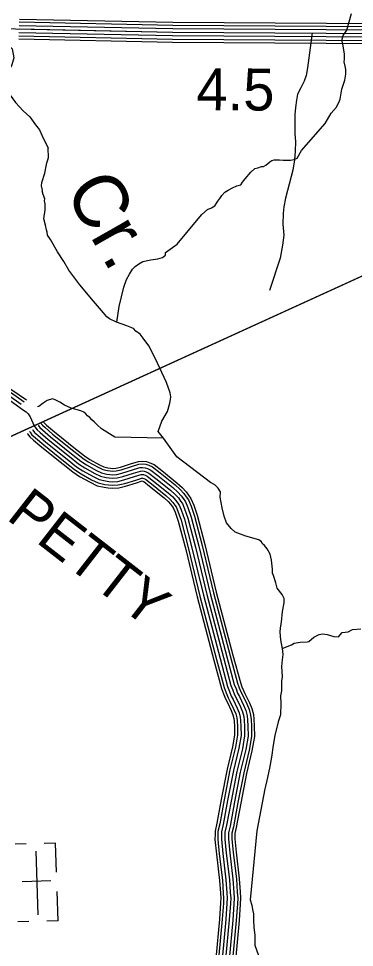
# Model space of a CAD drawing. Extents: x 1577619 to 1828281, y 483481 to 598136.
# Drawn here: x 1672781 to 1675742, y 510126 to 518314 of the extents above; entities that cross this region are included whole.
import ezdxf

# ---------------------------------------------------------------- set-up
doc = ezdxf.new("R2010")
doc.units = 0
for name, color, linetype in [('DESIGN - CENTERLINE - Proposed Text', 7, 'Continuous'), ('DESIGN - DRAINAGE - Bridges and Cross Drains Size Text', 7, 'Continuous'), ('DESIGN - ROW - Right-of-Way and Easement Labels', 7, 'Continuous'), ('DESIGN - TRAFFIC CONTROL PERMANENT - Signalization', 7, 'Continuous'), ('DESIGN - TRANSPORTATION - Text', 7, 'Continuous'), ('DESIGN - UTILITIES - Cable (Underground) with Text', 7, 'Continuous'), ('SURVEY - CONTROL with Text', 7, 'Continuous'), ('SURVEY - DRAINAGE - Area Shapes', 7, 'Continuous'), ('SURVEY - TRANSPORTATION - Roads', 7, 'Continuous')]:
    doc.layers.add(name, color=color, linetype=linetype)

msp = doc.modelspace()

# ---------------------------------------------------------------- linework, layer by layer
at = {"layer": 'DESIGN - CENTERLINE - Proposed Text'}
for points in [[(1680380.8, 518130.9), (1666391, 511745.9), (1653607.1, 511745.9)], [(1680380.8, 518130.9), (1669171.5, 513015)]]:
    msp.add_lwpolyline(points, dxfattribs=at)
at = {"layer": 'DESIGN - TRANSPORTATION - Text'}
for points in [[(1675276.4, 517151), (1675483.1, 517387.5), (1675538, 517479.2), (1675580.6, 517530.9), (1675603.7, 517574.3), (1675617.4, 517602.7), (1675630.4, 517692.8), (1675657.2, 517770.7), (1675667.8, 517822.7), (1675666.2, 517864.9), (1675660.5, 517893), (1675652.9, 517933.2), (1675653.2, 517957.3), (1675653.7, 518003.4), (1675650, 518035.5), (1675638.6, 518091.8), (1675630.9, 518119.9), (1675643.4, 518163.9), (1675673.9, 518211.7), (1675717.5, 518359.7)], [(1672669.3, 518102.8), (1672725.2, 518045.9), (1672738.7, 517968.5), (1672722.9, 517905.8), (1672688.3, 517854), (1672670, 517820.1), (1672659.4, 517768.1), (1672657.1, 517740.6), (1672684.4, 517671.6), (1672755.4, 517574.6), (1672822.7, 517501.7), (1672880.2, 517448.9), (1672929.4, 517378.2), (1672965, 517331.7), (1672986.5, 517285.4), (1673043.3, 517170.4)], [(1675107.4, 512757.3), (1675093.7, 512837.7), (1675086.5, 512903.9), (1675088.9, 512943.9), (1675099.5, 512991.9), (1675106.6, 513087.9), (1675121.5, 513163.8), (1675124, 513201.8), (1675106.4, 513238.1), (1675061.1, 513292.7), (1675049.7, 513340.9), (1675028.5, 513405.2), (1675020.8, 513425.3), (1675021.2, 513461.4), (1675012.2, 513539.6), (1674998.8, 513591.8), (1674971.4, 513638.2), (1674949.8, 513668.5), (1674930, 513686.8), (1674922.2, 513700.9), (1674898.5, 513719.2), (1674785, 513750.6), (1674689.6, 513785.8), (1674656, 513818.3), (1674614.7, 513868.9), (1674593.4, 513927.2), (1674576.3, 514001.5), (1674557.5, 514095.8), (1674560, 514141.9), (1674540.5, 514174.1), (1674510.9, 514204.5), (1674473.2, 514225), (1674177.4, 514449.6), (1674058.5, 514613.8), (1674011.2, 514675.2), (1674044.3, 514764.9), (1674093.2, 514850.4), (1674114, 514922.3), (1674120.4, 514956.2), (1674122.7, 514980.2), (1674117.1, 515014.3), (1674086.3, 515104.8), (1673985, 515320.3), (1673930.4, 515429.1), (1673879.2, 515495.8), (1673851.7, 515532.2), (1673814.1, 515558.7), (1673794.4, 515581), (1673734.8, 515605.7), (1673645.3, 515636.9), (1673583.7, 515665.7), (1673558, 515686), (1673530.5, 515720.4), (1673441.8, 515823.6), (1673319.7, 515965.3), (1673223.4, 516094.6), (1673180.4, 516171.2), (1673123.5, 516258), (1673062.9, 516364.9), (1673037.4, 516403.3), (1673031.7, 516431.4), (1673025.9, 516451.5), (1673018.4, 516491.6), (1673005.2, 516549.8), (1673016.1, 516627.8), (1673016.7, 516679.8), (1673011, 516707.9), (1673011.2, 516726), (1672997.7, 516762.2), (1672990.1, 516794.3), (1672992.2, 516802.3), (1672982.6, 516838.4), (1672987, 516868.4), (1673011.9, 516952.2), (1673024.7, 517014.1), (1673031, 517042.1), (1673039.3, 517068), (1673043.5, 517090), (1673043.3, 517170.4)], [(1673646.4, 515636.5), (1673668.9, 515776.7), (1673708.9, 515946.5), (1673731.6, 516014.2), (1673758.1, 516060), (1673784.6, 516103.7), (1673808.9, 516129.4), (1673841.1, 516153.1), (1673877.3, 516172.6), (1673947.4, 516187.8), (1674007.4, 516195.1), (1674049.5, 516208.6), (1674077.7, 516228.2), (1674077.9, 516250.3), (1674178.7, 516325.1), (1674350.9, 516531.2), (1674395.4, 516586.7), (1674447.9, 516630.2), (1674482, 516645.7), (1674510.2, 516663.4), (1674536.6, 516705.2), (1674556.9, 516728.9), (1674573.2, 516754.8), (1674599.5, 516782.5), (1674629.6, 516800.1), (1674667.8, 516821.7), (1674706, 516839.2), (1674740, 516848.8), (1674756.3, 516872.6), (1674778.6, 516902.4), (1674829.2, 516959.8), (1674863.6, 516993.5), (1674889.6, 516999.1), (1674921.7, 517008.8), (1674939.7, 517010.5), (1674959.8, 517022.3), (1674996, 517049.9), (1675014.2, 517063.7), (1675034.2, 517067.4), (1675080.1, 517068.9), (1675114, 517064.5), (1675150, 517066), (1675179.9, 517065.7), (1675210, 517071.3), (1675236.1, 517083), (1675276.4, 517151)], [(1674058.5, 514613.8), (1673628.3, 514623.8), (1673513.2, 514697.1), (1673473.6, 514731.6), (1673451.9, 514755.8), (1673428.2, 514778.1), (1673410.4, 514796.3), (1673388.6, 514812.6), (1673372.8, 514828.8), (1673356.9, 514845), (1673329.1, 514855.3), (1673243.5, 514880.2), (1673185.8, 514906.8), (1673146.2, 514931.3), (1673108.4, 514949.7), (1673082.6, 514962), (1673050.5, 514954.3), (1673032.5, 514946.5), (1672998.3, 514924.8), (1672960.1, 514895.1), (1672948.6, 514889.8)], [(1675104.7, 512762.1), (1675187, 512792.5), (1675211.1, 512808.3), (1675263.1, 512815.6), (1675325.1, 512820.9), (1675339.1, 512822.7), (1675385.5, 512862.2), (1675431.7, 512885.6), (1675459.7, 512889.3), (1675501.6, 512884.8), (1675559.3, 512868), (1675601.2, 512863.5), (1675633.6, 512903.2), (1675687.6, 512906.5), (1675725.8, 512928.1), (1675799.7, 512935.2)], [(1675104.7, 512762.1), (1675111.2, 512708.4), (1675105.5, 512661.4), (1675098.9, 512603.4), (1675105.7, 512511.2), (1675099.3, 512473.2), (1675098.3, 512387.2), (1675091.8, 512343.2), (1675093, 512275.1), (1675091.8, 512177), (1675069.1, 512115.2), (1675039.7, 511993.4), (1675026.7, 511909.5), (1675011.5, 511803.5), (1674992.3, 511705.7), (1674971.1, 511597.8), (1674958.5, 511545.9), (1674950.9, 511524.9), (1674881.8, 511154.9), (1674821.9, 510546.6)], [(1674821.9, 510546.6), (1674838.2, 510498.1), (1674843.7, 510460), (1674851.2, 510421.9), (1674852.6, 510365.8), (1674855.8, 510303.7)], [(1674855.8, 510303.7), (1674864.9, 510229.5), (1674863.9, 510145.4), (1674895.5, 510055.2), (1674900.9, 509995), (1674983.1, 509688), (1675005.1, 509529.1), (1674940.6, 509284.3)]]:
    msp.add_lwpolyline(points, dxfattribs=at)
at = {"layer": 'DESIGN - UTILITIES - Cable (Underground) with Text'}
for p, q in [((1672848.7, 511039.3), (1672749.7, 511035.8)), ((1673105.4, 511044.3), (1673005.7, 511040.8)), ((1673114.3, 510787.7), (1673105.3, 511044.3)), ((1673066.9, 510711.6), (1672813.4, 510702.7)), ((1673129.1, 510361.5), (1673120.1, 510619.4)), ((1672773.1, 510353), (1672871.3, 510356.4)), ((1673129, 510361.5), (1673029.6, 510358))]:
    msp.add_line(p, q, dxfattribs=at)
msp.add_lwpolyline([(1672932.3, 510974.8), (1672951.9, 510412.1)], dxfattribs=at)
at = {"layer": 'SURVEY - CONTROL with Text'}
for points in [[(1671784, 518243.6), (1674139.2, 518195.1), (1676396, 518179.9), (1677876.4, 518166), (1678638.8, 518166.9), (1678771.1, 518155.6), (1678959.5, 518137.8), (1679091.8, 518128.5), (1679416.8, 518129.5), (1679904.2, 518124.9), (1680622.4, 518118.1), (1681890.1, 518100.2)], [(1672786.5, 518254), (1674139.7, 518226.1), (1676396.3, 518210.9), (1677876.6, 518197), (1678564.1, 518197.8)], [(1672787.6, 518285), (1674140.1, 518257.1), (1676396.5, 518241.9), (1677876.7, 518228), (1678565.8, 518228.8)], [(1672788.5, 518309.7), (1674140.4, 518281.8), (1676396.7, 518266.6), (1677876.8, 518252.7), (1678567.1, 518253.5)], [(1672783.3, 518161), (1674138.4, 518133.1), (1676395.5, 518117.9), (1677876.2, 518104), (1678559.4, 518104.8)], [(1672784.3, 518192), (1674138.8, 518164.1), (1676395.8, 518148.9), (1677876.3, 518135), (1678560.8, 518135.8)], [(1672785.4, 518223), (1674139.2, 518195.1), (1676396, 518179.9), (1677876.4, 518166), (1678562.4, 518166.8)], [(1672782.5, 518135.3), (1674138, 518107.4), (1676395.3, 518092.2), (1677876.1, 518078.3), (1678558.1, 518079.1)]]:
    msp.add_lwpolyline(points, dxfattribs=at)
at = {"layer": 'SURVEY - DRAINAGE - Area Shapes'}
msp.add_lwpolyline([(1675369.1, 518186.8), (1675328.5, 517878.9), (1675315.9, 517810.8), (1675298.2, 517762), (1675268.7, 517701.9), (1675240.6, 517647.8), (1675230.5, 517593.7), (1675222, 517531.3), (1675216.9, 517467.3), (1675216.1, 517391.6), (1675217.8, 517299.9), (1675222.4, 517227.6), (1675218.8, 517145.6), (1675215.2, 517068.4), (1675198.4, 516976.6), (1675153.4, 516797.8), (1675133.4, 516732.2), (1675120, 516655.1), (1675114.1, 516596.3), (1675111.2, 516502.5), (1675119, 516404), (1675107.1, 516317), (1675086.9, 516202.2), (1674992.3, 515916.9)], dxfattribs=at)
at = {"layer": 'SURVEY - TRANSPORTATION - Roads'}
for points in [[(1671737.9, 515296.7), (1672126.4, 515196.9), (1672340.1, 515137.8), (1672472.3, 515096.9), (1672595.2, 515054.8), (1672631.9, 515032.5), (1672692.2, 514995.1), (1672804.6, 514915.8)], [(1671745.6, 515326.7), (1672134.4, 515226.8), (1672348.8, 515167.5), (1672481.9, 515126.4), (1672608.4, 515083), (1672648.1, 515058.9), (1672709.3, 515020.9), (1672831.3, 514934.9)], [(1671751.8, 515350.6), (1672140.7, 515250.7), (1672355.7, 515191.2), (1672489.5, 515149.9), (1672619, 515105.5), (1672661, 515080), (1672723, 515041.6), (1672850.5, 514951.6)], [(1672675.1, 514969.2), (1672825.5, 514863.1), (1672847.6, 514846.9), (1672866.2, 514828.2), (1672884.7, 514804.2), (1672919.6, 514723.6), (1672932.9, 514704.1), (1672945.1, 514687.2), (1672970.8, 514664.9), (1673041.9, 514603.8), (1673229.7, 514453.1), (1673310.7, 514387.9), (1673364.2, 514353.2), (1673453.5, 514303.9), (1673503.1, 514279.2), (1673552.9, 514268.5), (1673580.8, 514264.2), (1673608.7, 514261.8), (1673650.7, 514265.2), (1673700.8, 514276.6), (1673795.1, 514305.4), (1673855.2, 514324.6), (1673873.2, 514326.3), (1673889.2, 514324.1), (1673907.1, 514317.9), (1673930.9, 514307.5), (1673990.2, 514260.7), (1674120.7, 514156.8), (1674162.2, 514118.2), (1674189.7, 514087.8), (1674209.1, 514061), (1674225.1, 514039.3), (1674244.4, 513992.9), (1674273.3, 513910.4), (1674339.9, 513655.2), (1674440.3, 513237.3), (1674586.9, 512680.6), (1674653.6, 512435.4), (1674669.1, 512393.1), (1674684.5, 512352.9), (1674700.1, 512324.6), (1674737.1, 512248), (1674754.5, 512203.7), (1674765.9, 512161.5), (1674769.5, 512129.4), (1674772.8, 512075.3), (1674773.7, 511991.2), (1674754, 511877.4), (1674705.7, 511677.7), (1674654.3, 511414), (1674615.6, 511202.2), (1674600.8, 511140.3), (1674600.6, 511122.3), (1674600, 511080.3), (1674612.4, 510956), (1674639.3, 510723.3), (1674647.8, 510609), (1674651.2, 510560.9), (1674648.5, 510512.9), (1674638.7, 510368.8), (1674606.2, 510020.8)], [(1672928, 514711.3), (1672932.9, 514704.1), (1672945.1, 514687.2), (1672970.8, 514664.9), (1673041.9, 514603.8), (1673229.7, 514453.1), (1673310.7, 514387.9), (1673364.2, 514353.2), (1673453.5, 514303.9), (1673503.1, 514279.2), (1673552.9, 514268.5), (1673580.8, 514264.2), (1673608.7, 514261.8), (1673650.7, 514265.2), (1673700.8, 514276.6), (1673795.1, 514305.4), (1673855.2, 514324.6), (1673873.2, 514326.3), (1673889.2, 514324.1), (1673907.1, 514317.9), (1673930.9, 514307.5), (1673990.2, 514260.7), (1674120.7, 514156.8), (1674162.2, 514118.2), (1674189.7, 514087.8), (1674209.1, 514061), (1674225.1, 514039.3), (1674244.4, 513992.9), (1674273.3, 513910.4), (1674339.9, 513655.2), (1674440.3, 513237.3), (1674586.9, 512680.6), (1674653.6, 512435.4), (1674669.1, 512393.1), (1674684.5, 512352.9), (1674700.1, 512324.6), (1674737.1, 512248), (1674754.5, 512203.7), (1674765.9, 512161.5), (1674769.5, 512129.4), (1674772.8, 512075.3), (1674773.7, 511991.2), (1674754, 511877.4), (1674705.7, 511677.7), (1674654.3, 511414), (1674615.6, 511202.2), (1674600.8, 511140.3), (1674600.6, 511122.3), (1674600, 511080.3), (1674612.4, 510956), (1674639.3, 510723.3), (1674647.8, 510609), (1674651.2, 510560.9), (1674648.5, 510512.9), (1674638.7, 510368.8), (1674606.2, 510020.8)], [(1672952.8, 514730), (1672958.3, 514722), (1672968.1, 514708.3), (1672991.1, 514688.3), (1673061.7, 514627.7), (1673249.1, 514477.3), (1673329, 514413.1), (1673380.2, 514379.8), (1673467.9, 514331.4), (1673513.4, 514308.7), (1673558.6, 514299), (1673584.5, 514295), (1673608.8, 514292.9), (1673646, 514295.9), (1673692.9, 514306.6), (1673785.8, 514334.9), (1673849, 514355.1), (1673873.9, 514357.5), (1673896.5, 514354.4), (1673918.4, 514346.8), (1673947, 514334.4), (1674009.5, 514285), (1674141, 514180.3), (1674184.3, 514140), (1674213.9, 514107.3), (1674234.1, 514079.3), (1674252.2, 514054.6), (1674273.4, 514004), (1674303, 513919.5), (1674370, 513662.7), (1674470.4, 513244.9), (1674616.9, 512688.6), (1674683.2, 512444.8), (1674698.1, 512404), (1674712.7, 512366), (1674727.7, 512338.9), (1674765.5, 512260.4), (1674783.9, 512213.5), (1674796.4, 512167.3), (1674800.4, 512132.1), (1674803.8, 512076.4), (1674804.7, 511988.7), (1674784.4, 511871.1), (1674736, 511671.1), (1674684.7, 511408.3), (1674645.9, 511195.8), (1674631.7, 511136.5), (1674631.6, 511121.9), (1674631, 511081.6), (1674643.2, 510959.3), (1674670.2, 510726.2), (1674678.7, 510611.2), (1674682.2, 510561.1), (1674679.5, 510511), (1674669.6, 510366.3), (1674637, 510017.9)], [(1672977.3, 514749), (1672983.6, 514739.8), (1672991.2, 514729.3), (1673011.3, 514711.8), (1673081.5, 514651.5), (1673268.5, 514501.4), (1673347.2, 514438.2), (1673396.1, 514406.4), (1673482.3, 514358.8), (1673523.7, 514338.2), (1673564.2, 514329.5), (1673588.2, 514325.8), (1673608.8, 514324), (1673641.3, 514326.7), (1673684.9, 514336.5), (1673776.6, 514364.5), (1673842.7, 514385.6), (1673874.5, 514388.8), (1673903.8, 514384.7), (1673929.7, 514375.7), (1673963, 514361.2), (1674028.8, 514309.3), (1674161.2, 514203.8), (1674206.3, 514161.8), (1674238, 514126.9), (1674259.2, 514097.5), (1674279.4, 514070), (1674302.3, 514015.2), (1674332.7, 513928.5), (1674400.1, 513670.3), (1674500.5, 513252.4), (1674646.8, 512696.6), (1674712.7, 512454.2), (1674727.1, 512414.9), (1674740.8, 512379.1), (1674755.2, 512353.1), (1674793.9, 512272.9), (1674813.4, 512223.2), (1674827, 512173.1), (1674831.3, 512134.7), (1674834.8, 512077.5), (1674835.7, 511986.2), (1674814.8, 511864.8), (1674766.3, 511664.4), (1674715.2, 511402.5), (1674676.3, 511189.4), (1674662.7, 511132.6), (1674662.5, 511121.5), (1674662, 511083), (1674674, 510962.6), (1674701, 510729.1), (1674709.6, 510613.5), (1674713.3, 510561.4), (1674710.4, 510509.1), (1674700.5, 510363.8), (1674667.9, 510015.1)], [(1672996.5, 514764.8), (1673003.9, 514754), (1673009.6, 514746.1), (1673027.5, 514730.4), (1673097.3, 514670.6), (1673284, 514520.7), (1673361.7, 514458.3), (1673408.9, 514427.6), (1673493.8, 514380.7), (1673532, 514361.7), (1673568.7, 514353.8), (1673591.2, 514350.3), (1673608.9, 514348.8), (1673637.5, 514351.2), (1673678.5, 514360.4), (1673769.2, 514388.1), (1673837.6, 514410), (1673875, 514413.6), (1673909.7, 514408.8), (1673938.7, 514398.7), (1673975.8, 514382.6), (1674044.1, 514328.6), (1674177.4, 514222.6), (1674224, 514179.2), (1674257.2, 514142.5), (1674279.2, 514112.1), (1674301.1, 514082.3), (1674325.4, 514024), (1674356.3, 513935.8), (1674424, 513676.3), (1674524.4, 513258.5), (1674670.7, 512703), (1674736.3, 512461.7), (1674750.3, 512423.5), (1674763.3, 512389.5), (1674777.2, 512364.5), (1674816.6, 512282.8), (1674836.9, 512231), (1674851.3, 512177.7), (1674855.9, 512136.9), (1674859.5, 512078.4), (1674860.5, 511984.2), (1674839, 511859.8), (1674790.4, 511659.2), (1674739.5, 511397.9), (1674700.5, 511184.3), (1674687.4, 511129.6), (1674687.3, 511121.2), (1674686.8, 511084), (1674698.6, 510965.2), (1674725.7, 510731.5), (1674734.3, 510615.3), (1674738.1, 510561.6), (1674735.1, 510507.5), (1674725.1, 510361.8), (1674692.5, 510012.8)], [(1672859.4, 514656.2), (1672861.1, 514653.7), (1672879.9, 514627.7), (1672913.4, 514598.5), (1672985.9, 514536.3), (1673174.8, 514384.7), (1673259.2, 514316.8), (1673319.1, 514277.9), (1673412.7, 514226.2), (1673473.9, 514195.8), (1673536.9, 514182.3), (1673570.3, 514177), (1673608.6, 514173.8), (1673664.1, 514178.3), (1673723.3, 514191.7), (1673821.2, 514221.6), (1673871.1, 514237.5), (1673875.2, 514236.1), (1673885.5, 514231.6), (1673935.7, 514192), (1674063.4, 514090.3), (1674099.7, 514056.5), (1674121.5, 514032.5), (1674138.2, 514009.4), (1674148.2, 513995.7), (1674162.5, 513961.5), (1674189.4, 513884.8), (1674254.8, 513633.9), (1674355.3, 513215.9), (1674502.2, 512657.9), (1674570, 512408.8), (1674586.9, 512362.4), (1674604.8, 512315.7), (1674622.2, 512284.3), (1674656.6, 512212.9), (1674671.1, 512176.1), (1674679.5, 512145.1), (1674682.1, 512121.9), (1674685.1, 512072.2), (1674685.9, 511998.2), (1674668.1, 511895.2), (1674620, 511696.4), (1674568.1, 511430.3), (1674529.7, 511220.3), (1674513.2, 511151.2), (1674512.9, 511123.5), (1674512.2, 511076.5), (1674525.2, 510946.6), (1674552, 510715), (1674560.3, 510602.7), (1674563.3, 510560.2), (1674561, 510518.3), (1674551.2, 510375.9), (1674518.8, 510028.8)], [(1672878.8, 514673.4), (1672882.1, 514668.5), (1672899, 514645.2), (1672930.2, 514618), (1673002.3, 514556.1), (1673190.9, 514404.8), (1673274.3, 514337.7), (1673332.3, 514300), (1673424.7, 514249), (1673482.5, 514220.2), (1673541.6, 514207.6), (1673573.4, 514202.6), (1673608.6, 514199.6), (1673660.2, 514203.8), (1673716.7, 514216.6), (1673813.6, 514246.2), (1673867.8, 514263.5), (1673872, 514263.9), (1673874.6, 514263.6), (1673884.5, 514260.1), (1673898.9, 514253.9), (1673951.7, 514212.1), (1674080.2, 514109.8), (1674118, 514074.6), (1674141.5, 514048.7), (1674158.9, 514024.5), (1674170.7, 514008.5), (1674186.5, 513970.7), (1674214, 513892.3), (1674279.8, 513640.1), (1674380.2, 513222.2), (1674527, 512664.6), (1674594.5, 512416.6), (1674611, 512371.4), (1674628.2, 512326.6), (1674645, 512296.1), (1674680.2, 512223.2), (1674695.5, 512184.2), (1674704.8, 512149.9), (1674707.7, 512124.1), (1674710.8, 512073.1), (1674711.6, 511996.2), (1674693.3, 511890), (1674645.1, 511690.9), (1674593.4, 511425.5), (1674554.9, 511215), (1674538.9, 511148), (1674538.6, 511123.1), (1674538, 511077.6), (1674550.7, 510949.3), (1674577.6, 510717.4), (1674586, 510604.5), (1674589.1, 510560.4), (1674586.7, 510516.7), (1674576.9, 510373.8), (1674544.4, 510026.5)], [(1672904, 514691.5), (1672907.5, 514686.3), (1672922.1, 514666.2), (1672950.5, 514641.4), (1673022.1, 514580), (1673210.3, 514428.9), (1673292.5, 514362.8), (1673348.3, 514326.6), (1673439.1, 514276.5), (1673492.8, 514249.7), (1673547.2, 514238.1), (1673577.1, 514233.4), (1673608.7, 514230.7), (1673655.4, 514234.5), (1673708.8, 514246.6), (1673804.3, 514275.8), (1673861.5, 514294), (1673872.6, 514295.1), (1673881.9, 514293.8), (1673895.8, 514289), (1673914.9, 514280.7), (1673971, 514236.4), (1674100.5, 514133.3), (1674140.1, 514096.4), (1674165.6, 514068.2), (1674184, 514042.8), (1674197.9, 514023.9), (1674215.5, 513981.8), (1674243.7, 513901.4), (1674309.8, 513647.7), (1674410.3, 513229.7), (1674557, 512672.6), (1674624.1, 512426), (1674640, 512382.2), (1674656.3, 512339.7), (1674672.6, 512310.4), (1674708.6, 512235.6), (1674725, 512194), (1674735.4, 512155.7), (1674738.6, 512126.8), (1674741.8, 512074.2), (1674742.6, 511993.7), (1674723.7, 511883.7), (1674675.4, 511684.3), (1674623.8, 511419.8), (1674585.2, 511208.6), (1674569.8, 511144.2), (1674569.6, 511122.7), (1674569, 511078.9), (1674581.6, 510952.6), (1674608.4, 510720.3), (1674616.9, 510606.8), (1674620.1, 510560.7), (1674617.6, 510514.8), (1674607.8, 510371.3), (1674575.3, 510023.6)]]:
    msp.add_lwpolyline(points, dxfattribs=at)

# ---------------------------------------------------------------- texts
at = {"layer": 'DESIGN - DRAINAGE - Bridges and Cross Drains Size Text'}
msp.add_text('Cr.', height=475.01, rotation=299.56821, dxfattribs=at).set_placement((1673181.7, 516797.8))
at = {"layer": 'DESIGN - ROW - Right-of-Way and Easement Labels'}
msp.add_text('PETTY', height=370, rotation=322.13903, dxfattribs=at).set_placement((1672664.3, 513907))
at = {"layer": 'DESIGN - TRAFFIC CONTROL PERMANENT - Signalization'}
msp.add_text('4.5', height=369.99, rotation=359.61484, dxfattribs=at).set_placement((1674348.3, 517507.1))

doc.saveas('drawing.dxf')
